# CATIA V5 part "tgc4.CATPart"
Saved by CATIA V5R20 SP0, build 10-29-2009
Part number: TGC4
Revision: 17
Definition: design
Nomenclature: TGC4
Source: made
Description: NOT SPECIFIED
Bounding box of the stored display mesh (mm): x -3.8 to 41.2, y -6 to 6, z -26 to 10
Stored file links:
  C:\Users\Utente\Desktop\IO LAVORO\3D X SITO CF\X SITO\PLASTICA\TGC-XS\tgc4.CATPart
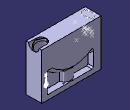
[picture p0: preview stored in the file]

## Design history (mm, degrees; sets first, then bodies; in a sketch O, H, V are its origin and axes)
Set1
  Line1 "LINE #7945": stored without definition
  Circle1 "COMPOSITE_CURVE #7962": stored without definition
  Circle2 "COMPOSITE_CURVE #7977": stored without definition
  DatumCurve1 "COMPOSITE_CURVE #8141"
  DatumCurve2 "COMPOSITE_CURVE #8166"
  DatumCurve3 "COMPOSITE_CURVE #8193"
  DatumCurve4 "COMPOSITE_CURVE #8219"
  DatumCurve5 "COMPOSITE_CURVE #8273"
  DatumCurve6 "COMPOSITE_CURVE #8300"
  DatumCurve7 "COMPOSITE_CURVE #8325"
  DatumCurve8 "COMPOSITE_CURVE #8442"
  DatumCurve9 "COMPOSITE_CURVE #8469"
  Circle3 "COMPOSITE_CURVE #8477": stored without definition
  Circle4 "COMPOSITE_CURVE #8485": stored without definition
  Circle5 "COMPOSITE_CURVE #8493": stored without definition
  Circle6 "COMPOSITE_CURVE #8501": stored without definition
  Point1 "CARTESIAN_POINT #8502": stored without definition
  Point2 "CARTESIAN_POINT #8503": stored without definition
  Point3 "CARTESIAN_POINT #8504": stored without definition
  Point4 "CARTESIAN_POINT #8505": stored without definition
  Point5 "CARTESIAN_POINT #8506": stored without definition
  Point6 "CARTESIAN_POINT #8507": stored without definition
  Point7 "CARTESIAN_POINT #8508": stored without definition
  Point8 "CARTESIAN_POINT #8509": stored without definition
  Point9 "CARTESIAN_POINT #8510": stored without definition
  Point10 "CARTESIAN_POINT #8511": stored without definition
  Point11 "CARTESIAN_POINT #8512": stored without definition
  Point12 "CARTESIAN_POINT #8513": stored without definition
  Point13 "CARTESIAN_POINT #8514": stored without definition
  Point14 "CARTESIAN_POINT #8515": stored without definition
  Point15 "CARTESIAN_POINT #8516": stored without definition
  Circle7 "COMPOSITE_CURVE #8524": stored without definition
  Circle8 "COMPOSITE_CURVE #8532": stored without definition
  Circle9 "COMPOSITE_CURVE #8540": stored without definition
  Circle10 "COMPOSITE_CURVE #8548": stored without definition
  DatumSurface1 "OPEN_SHELL #7459"
  DatumSurface2 "OPEN_SHELL #7698"
  DatumSurface3 "OPEN_SHELL #7817"
  DatumSurface4 "OPEN_SHELL #7935"
Body1 "MANIFOLD_SOLID_BREP #7936" (main body)
  Solid1: solid without history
